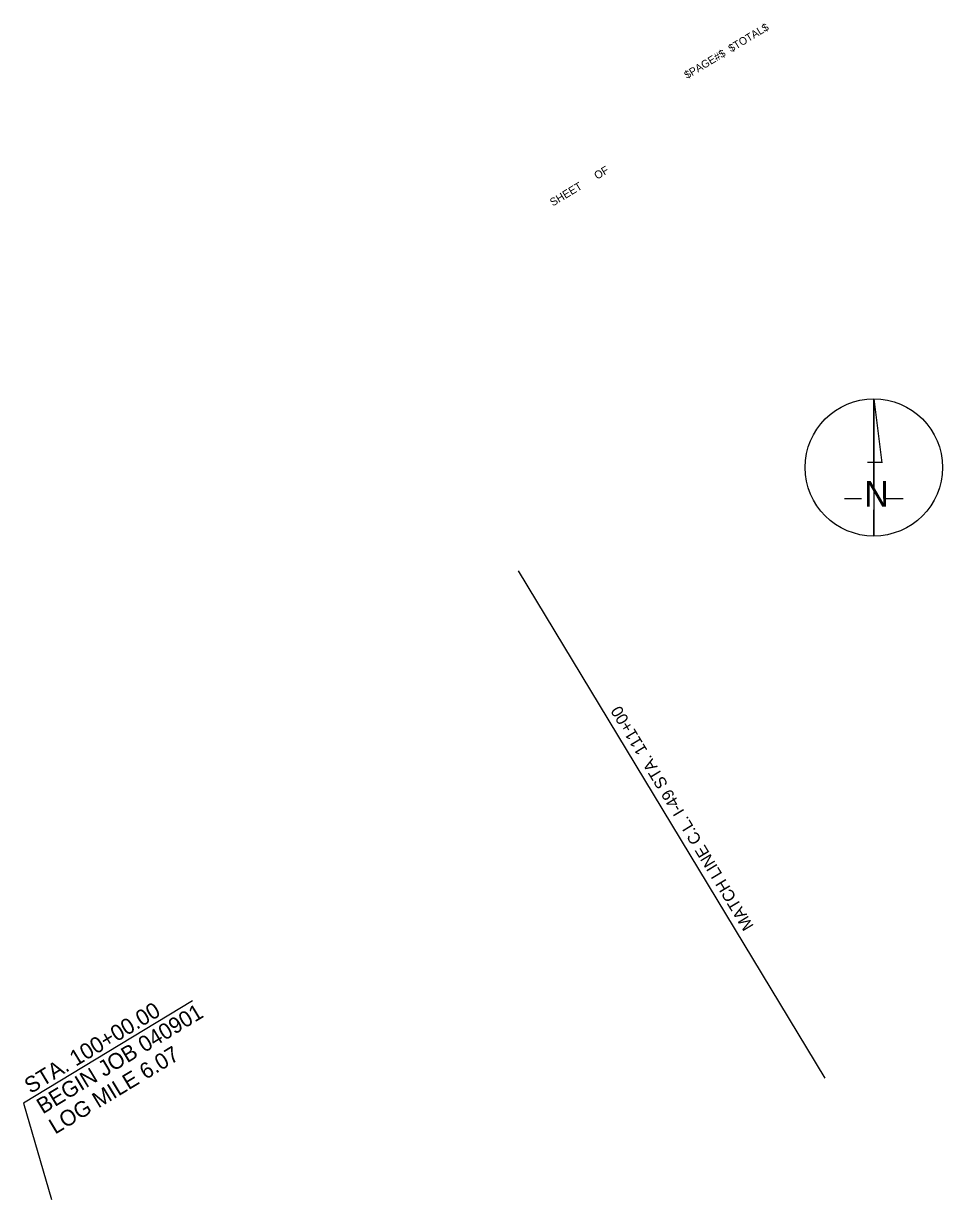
# Model space of a CAD drawing. Extents: x 629051 to 630445, y 368162 to 369946.
import ezdxf

# ---------------------------------------------------------------- set-up
doc = ezdxf.new("R2010")
doc.units = 0
for name, color, linetype in [('R_Border', 7, 'Continuous'), ('R_Border Notes', 7, 'Continuous'), ('R_Border_N Arrow', 7, 'Continuous'), ('R_Border_Scale', 7, 'Continuous'), ('R_Draft', 7, 'Continuous'), ('R_No Plot', 7, 'Continuous')]:
    doc.layers.add(name, color=color, linetype=linetype)

# ---------------------------------------------------------------- blocks, each defined once
blk = doc.blocks.new('SHT-INFO-CELL')
at = {"layer": 'R_No Plot'}
for s, p in [('SHEET', (14.4405, 10.0545)), ('OF', (14.8333, 10.0545))]:
    blk.add_text(s, height=0.06, dxfattribs=at).set_placement(p)

msp = doc.modelspace()

# ---------------------------------------------------------------- linework, layer by layer
at = {"layer": 'R_Border'}
msp.add_line((630267.1, 368345.8), (629801.4, 369115.9), dxfattribs=at)
at = {"layer": 'R_Border_N Arrow'}
for p, q in [((630340.7, 369376.8), (630352.9, 369279.9)), ((630340.7, 369241.2), (630340.7, 369376.8)), ((630331.3, 369280.6), (630352.9, 369280.6)), ((630296.1, 369225.3), (630321.9, 369225.3)), ((630357.8, 369225.3), (630385.3, 369225.3)), ((630340.7, 369168.5), (630340.7, 369208.4))]:
    msp.add_line(p, q, dxfattribs=at)
at = {"layer": 'R_Draft'}
for p, q in [((629306.9, 368462.9), (629050.6, 368307.8)), ((629050.6, 368307.8), (629093, 368161.6))]:
    msp.add_line(p, q, dxfattribs=at)
at = {"layer": 'R_No Plot'}
msp.add_line((630340.7, 369376.8), (630340.7, 369168.5), dxfattribs=at)
msp.add_circle((630340.7, 369272.7), 104.2, dxfattribs=at)

# ---------------------------------------------------------------- block references
at = {"layer": 'R_Border_Scale', "xscale": 199.99999999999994, "yscale": 199.99999999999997, "rotation": 31.163797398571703}
msp.add_blockref('SHT-INFO-CELL', (628423, 366453.3), dxfattribs=at)

# ---------------------------------------------------------------- texts
at = {"layer": 'R_Border'}
for s, p in [('$TOTAL$', (630124.4, 369902.4)), ('$PAGE#$', (630057.5, 369861.9))]:
    msp.add_text(s, height=11.72, rotation=31.1638, dxfattribs=at).set_placement(p)
at = {"layer": 'R_Border Notes'}
msp.add_text('MATCH LINE C.L. I-49 STA. 111+00', height=18, rotation=121.1638, dxfattribs=at).set_placement((630159.1, 368576.6))
at = {"layer": 'R_Border_N Arrow'}
msp.add_text('N', height=38.8, rotation=360, dxfattribs=at).set_placement((630326, 369213.3))
at = {"layer": 'R_Draft'}
for s, p in [('STA. 100+00.00', (629061.2, 368321.5)), ('BEGIN JOB 040901', (629079.8, 368290.7)), ('LOG MILE 6.07', (629098.5, 368259.9))]:
    msp.add_text(s, height=24, rotation=31.1638, dxfattribs=at).set_placement(p)

doc.saveas('drawing.dxf')
